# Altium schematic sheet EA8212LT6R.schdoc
size 127 x 101 mm
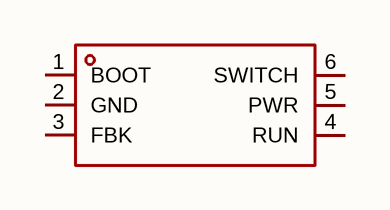
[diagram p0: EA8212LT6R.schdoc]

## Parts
U?  ea8212lt6r  [SOT-23-6_L2.9-W1.6-P0.95-LS2.8-BR]  (value not drawn)

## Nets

Not connected (* = marked no-connect by the designer): U? 1(BOOT) 2(GND) 3(FBK) 4(RUN) 5(PWR) 6(SWITCH)

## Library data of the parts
U? = ea8212lt6r: 功能类型:降压型;工作电压:4.5V~16V;输出电压:600mV~9V;输出电流:2A;输出类型:可调;; Manufacturer: everanalog(申风); AddInBom: yes; ModelId: 18da8f6c14a34920b3e136b5c401a119; ModelName: SOT-23-6_L2.9-W1.6-H1.5-LS2.8-P0.95; ModelTransform: 110.73671,114.173,0,180,0,0,0.001,-0.003,0; Function: 降压型; Output Current: 2A; Frequency - Switching: 600kHz; Synchronous Rectifier: 是; Number of Outputs: 1; Topology: 降压式; Quiescent Current: 300uA; Switch tube (built-in/external): 内置; Output Type: 可调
